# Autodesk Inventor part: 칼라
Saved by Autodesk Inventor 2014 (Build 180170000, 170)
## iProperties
Created: 2026-08
Part Number: 칼라
Material: 강철, 연강
Document SubType Name: Modeling
Designer: dg
Density: 7.86 g/cm^3
Appearance: 강철
Mass: 5.35836 g
Surface Area: 8.28117 cm^2
Volume: 0.681726 cm^3
Author: jhkim
Creation Date: 2026-07-31
Sending System: Autodesk Inventor 2027
Preprocessor: ST-DEVELOPER v20.1
Author: dg
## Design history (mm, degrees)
node "칼라1"
node "솔리드1"
node "기준1"
